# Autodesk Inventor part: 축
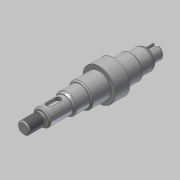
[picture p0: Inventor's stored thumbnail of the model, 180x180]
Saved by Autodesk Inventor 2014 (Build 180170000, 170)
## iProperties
Created: 2019-09
Part Number: 축
Material: 강철, 연강
Document SubType Name: Modeling
Designer: mduedu
Density: 7.86 g/cm^3
Mass: 210.278 g
Surface Area: 69.4769 cm^2
Volume: 26.7529 cm^3
Appearance: 강철
Author: mduedu
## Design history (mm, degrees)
sketch "스케치1"
  geometry: L1 (0, 0)-(15, 0); L2 (15, 0)-(15, 5); L3 (15, 5)-(0, 5); L4 (0, 5)-(0, 0); L5 (15, 0)-(34, 0); L6 (34, 0)-(34, 7); L7 (34, 7)-(15, 7); L8 (15, 7)-(15, 0); L9 (34, 0)-(47, 0); L10 (47, 0)-(47, 8.5); L11 (47, 8.5)-(34, 8.5); L12 (34, 8.5)-(34, 0); L13 (47, 0)-(63, 0); L14 (63, 0)-(63, 10); L15 (63, 10)-(47, 10); L16 (47, 10)-(47, 0); L17 (63, 0)-(75, 0); L18 (75, 0)-(75, 13.5); L19 (75, 13.5)-(63, 13.5); L20 (63, 13.5)-(63, 0); L21 (75, 0)-(90, 0); L22 (90, 0)-(90, 10); L23 (90, 10)-(75, 10); L24 (75, 10)-(75, 0); L25 (90, 0)-(102, 0); L26 (102, 0)-(102, 8.5); L27 (102, 8.5)-(90, 8.5); L28 (90, 8.5)-(90, 0); L29 (102, 0)-(111, 0); L30 (111, 0)-(111, 5.5); L31 (111, 5.5)-(102, 5.5); L32 (102, 5.5)-(102, 0)
  constraints: 64 end point, 16 parallel, 8 horizontal, 8 perpendicular
  dimensions: "d0" = 111 distance between parallel lines of L30 L4; "d2" = 15 distance of L2.end L3.end; "d3" = 19 distance of L6.end L7.end; "d4" = 12 distance of L18.end L19.end; "d5" = 15 distance of L22.end L23.end; "d6" = 12 distance of L26.end L27.end; "d7" = 9 distance of L30.end L31.end; "d8" = 16 distance of L14.end L15.end; "d9" = 10 diameter of L3 L1; "d10" = 14 diameter of L7 L5; "d11" = 17 diameter of L11 L9; "d12" = 20 diameter of L15 L13; "d13" = 27 diameter of L19 L17; "d14" = 20 diameter of L23 L21; "d15" = 17 diameter of L27 L25; "d16" = 11 diameter of L31 L29
revolve "회전1" sketch "스케치1" stored, may be unused: angle "d17" = 90 deg
sketch "스케치2"
  geometry: L1 (0, -5)-(0, 5) reference; L2 (0, 5)-(15, 5) reference; L3 (15, 5)-(15, 7) reference; L4 (15, 7)-(34, 7) reference; L5 (34, 7)-(34, 8.5) reference; L6 (34, 8.5)-(47, 8.5) reference; L7 (47, 8.5)-(47, 10) reference; L8 (47, 10)-(63, 10) reference; L9 (63, 10)-(63, 13.5) reference; L10 (63, 13.5)-(75, 13.5) reference; L11 (75, 13.5)-(75, 10) reference; L12 (75, 10)-(90, 10) reference; L13 (90, 10)-(90, 8.5) reference; L14 (90, 8.5)-(102, 8.5) reference; L15 (102, 8.5)-(102, 5.5) reference; L16 (102, 5.5)-(111, 5.5) reference; L17 (111, 5.5)-(111, -5.5) reference; L18 (111, -5.5)-(102, -5.5) reference; L19 (102, -5.5)-(102, -8.5) reference; L20 (102, -8.5)-(90, -8.5) reference; L21 (90, -8.5)-(90, -10) reference; L22 (90, -10)-(75, -10) reference; L23 (75, -10)-(75, -13.5) reference; L24 (75, -13.5)-(63, -13.5) reference; L25 (63, -13.5)-(63, -10) reference; L26 (63, -10)-(47, -10) reference; L27 (47, -10)-(47, -8.5) reference; L28 (47, -8.5)-(34, -8.5) reference; L29 (34, -8.5)-(34, -7) reference; L30 (34, -7)-(15, -7) reference; L31 (15, -7)-(15, -5) reference; L32 (15, -5)-(0, -5) reference; L33 (0, 0)-(111, 0); L34 (15, 5)-(12.014, 5); L35 (13.4, 4.2)-(15, 4.2); L36 (15, 4.2)-(15, 5); L37 (12.014, 5)-(13.4, 4.2)
  constraints: 10 end point, 1 horizontal, 1 midpoint, 1 parallel, 1 vertical
  dimensions: "d18" = 30 deg angle of L2 L37; "d19" = 8.4 diameter of L35 L33; "d21" = 2.986 distance from line of L34.end L36
revolve "회전2" sketch "스케치2" stored, may be unused: angle "d22" = 90 deg
fillet "모깎기1" dims "d23" = 0.6
feature "스레드1" dims "d24" = 10, "d25" = 0
chamfer "모따기1" distance "d26" = 1; stored, may be unused: second distance "d27" = 2, angle "d28" = 45 deg
chamfer "모따기2" distance "d29" = 1; stored, may be unused: second distance "d30" = 2, angle "d31" = 45 deg
chamfer "모따기3" distance "d32" = 1.819; stored, may be unused: second distance "d33" = 2, angle "d34" = 30 deg
fillet "모깎기2" dims "d35" = 2
chamfer "모따기4" distance "d36" = 1; stored, may be unused: second distance "d37" = 2, angle "d38" = 30 deg
fillet "모깎기3" dims "d39" = 0.3
chamfer "모따기5" distance "d40" = 1; stored, may be unused: second distance "d41" = 2, angle "d42" = 30 deg
chamfer "모따기6" distance "d43" = 1.819; stored, may be unused: second distance "d44" = 2, angle "d45" = 30 deg
chamfer "모따기7" distance "d46" = 0.5; stored, may be unused: second distance "d47" = 2, angle "d48" = 30 deg
fillet "모깎기4" dims "d49" = 2
node "작업 평면1"
sketch "스케치3" dims "d51" = 12
  geometry: L1 (3, -2.5)-(-4, -2.5); L2 (-4, -2.5)-(-4, 2.5); L3 (-4, 2.5)-(3, 2.5); L4 (3, 2.5)-(3, -2.5); L5 (-9.5, 7.45)-(-9.5, -7.45) reference; 3 further points
  constraints: 8 end point, 2 midpoint, 2 parallel, 2 vertical alignment, 1 horizontal, 1 horizontal alignment, 1 perpendicular, 4 other
  dimensions: "d50" = 3 dimension on L5; "d52" = 5 distance between parallel lines of L3 L1
extrude "돌출1" cut sketch "스케치3" distance "d53" = 3; taper "d54" = 0 deg
node "작업 평면3"
sketch "스케치4"
  geometry: L1 (-4.5, -5)-(-4.5, 5) reference; L2 (-4.5, -2)-(1.5, -2); L3 (1.5, -2)-(1.5, 2); L4 (1.5, 2)-(-4.5, 2); L5 (-4.5, 2)-(-4.5, -2); 3 further points
  constraints: 8 end point, 2 horizontal alignment, 2 midpoint, 2 parallel, 1 horizontal, 1 perpendicular, 1 point on line, 1 vertical alignment, 2 other
  dimensions: "d55" = 4 distance between parallel lines of L4 L2; "d57" = 8 dimension on L1
extrude "돌출2" cut sketch "스케치4" distance "d58" = 2.5; taper "d59" = 0 deg
sketch "스케치5"
  geometry: A1 r 5.5 centre (2, -3) between (0, 2.123) and (4, 2.123) reference; 2 further points
  constraints: 1 point on circle
hole "구멍1" sketch "스케치5" at (2, -8.5) diameter "d60" = 2.459; stored, may be unused: countersink angle "d64" = 90 deg, drill point angle "d66" = 118 deg; dims "d61" = 6, "d62" = 4, "d63" = 2, "d65" = 5
node "솔리드1"
node "절단 모서리 투영1"
